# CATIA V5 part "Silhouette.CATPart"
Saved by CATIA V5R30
Part number: Part1
Bounding box of the stored display mesh (mm): x -117 to 50, y -75 to 75, z 0 to 147
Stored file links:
  D:\PROJECTS\CATIA V56R 2020\Resources\Parts File\c17_catia_v6_6r2020_prt\Silhouette.CATPart
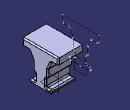
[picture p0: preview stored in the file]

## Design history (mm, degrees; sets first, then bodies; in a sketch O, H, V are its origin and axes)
Set1
  Sketch1 on yz-plane, origin (0, 0, 0), H (0, 1, 0), V (0, 0, 1)
    line L1 (0, 0) -> (45, 0)
    line L2 (45, 0) -> (45, 15)
    line L3 (45, 15) -> (22, 15)
    point P1 (45, 0)
    point P2 (45, 15)
    reference intersected line E1 through (0, 0) direction (0, 1) from zx-plane
    point P5 (0, 0)
    construction line L4 through (0, 0) direction (-1, 0)
    construction line L5 through (0, 0) direction (0, 1)
    point P6 (-45, 0)
    point P7 (-45, 15)
    line L6 (0, 0) -> (-45, 0)
    line L7 (-45, 0) -> (-45, 15)
    line L8 (-45, 15) -> (-22, 15)
    point P8 (-75, 147)
    line L9 (-75, 147) -> (75, 147)
    point P9 (75, 147)
    line L10 (75, 147) -> (75, 117)
    point P10 (75, 117)
    line L11 (75, 117) -> (45, 117)
    point P11 (45, 117)
    line L12 (45, 117) -> (30, 85)
    point P12 (30, 85)
    line L13 (30, 85) -> (30, 50)
    point P13 (30, 50)
    line L14 (30, 50) -> (22, 50)
    point P14 (22, 50)
    line L15 (22, 50) -> (22, 15)
    point P15 (22, 15)
    point P16 (-45, 15)
    point P17 (-75, 147)
    point P18 (-75, 117)
    point P19 (-45, 117)
    point P20 (-30, 85)
    point P21 (-30, 50)
    point P22 (-22, 50)
    point P23 (-22, 15)
    line L16 (-75, 147) -> (-75, 117)
    line L17 (-75, 117) -> (-45, 117)
    line L18 (-45, 117) -> (-30, 85)
    line L19 (-30, 85) -> (-30, 50)
    line L20 (-30, 50) -> (-22, 50)
    line L21 (-22, 50) -> (-22, 15)
    length L2 = 15
    length L10 = 30
    length L9 = 150
    length L11 = 30
    length L13 = 35
    length L15 = 35
    length L14 = 8
    distance P11 P12 V = 32
    distance P12 P11 H = 15
    horizontal: L1 H, L3 H, L9 H, L11 H, L14 H
    vertical: L2 V, L10 V, L13 V, L15 V
    symmetry: O P5 E1, H L4 E1, V L5 E1, P1 P6 E1, P2 P7 E1, L1 L6 E1, L2 L7 E1, L3 L8 E1, P2 P16 L5, P9 P17 L5, P10 P18 L5, P11 P19 L5, P12 P20 L5, P13 P21 L5, P14 P22 L5, P15 P23 L5, L10 L16 L5, L11 L17 L5, L12 L18 L5, L13 L19 L5, L14 L20 L5, L15 L21 L5, P9 P8 L5
    coincidence: P11 L2, O P5, P8 P17
Body1 (main body)
  Pad1: profile Sketch1, direction (1, 0, 0), length 50, mirrored extent
  Fillet1: radius 5, on edge [face of Pad1 from Sketch1.L10 | end face of Pad1]; edge [face of Pad1 from Sketch1.L16 | end face of Pad1]; edge [face of Pad1 from Sketch1.L17 | end face of Pad1]; edge [face of Pad1 from Sketch1.L18 | end face of Pad1]; edge [face of Pad1 from Sketch1.L19 | end face of Pad1]; edge [face of Pad1 from Sketch1.L20 | end face of Pad1]; edge [face of Pad1 from Sketch1.L21 | end face of Pad1]; edge [face of Pad1 from Sketch1.L8 | end face of Pad1]; edge [face of Pad1 from Sketch1.L3 | end face of Pad1]; edge [face of Pad1 from Sketch1.L15 | end face of Pad1]; edge [face of Pad1 from Sketch1.L14 | end face of Pad1]; end face of Pad1; edge [face of Pad1 from Sketch1.L10 | face of Pad1 from Sketch1.L11]; edge [face of Pad1 from Sketch1.L17 | face of Pad1 from Sketch1.L16]; edge [face of Pad1 from Sketch1.L11 | face of Pad1 from Sketch1.L12]; edge [face of Pad1 from Sketch1.L12 | face of Pad1 from Sketch1.L13]; edge [face of Pad1 from Sketch1.L13 | face of Pad1 from Sketch1.L14]; edge [face of Pad1 from Sketch1.L14 | face of Pad1 from Sketch1.L15]; edge [face of Pad1 from Sketch1.L15 | face of Pad1 from Sketch1.L3]; edge [face of Pad1 from Sketch1.L18 | face of Pad1 from Sketch1.L17]; edge [face of Pad1 from Sketch1.L19 | face of Pad1 from Sketch1.L18]; edge [face of Pad1 from Sketch1.L20 | face of Pad1 from Sketch1.L19]; edge [face of Pad1 from Sketch1.L21 | face of Pad1 from Sketch1.L20]; edge [face of Pad1 from Sketch1.L8 | face of Pad1 from Sketch1.L21]; face of Pad1 from Sketch1.L3; edge [face of Pad1 from Sketch1.L7 | face of Pad1 from Sketch1.L8]; edge [face of Pad1 from Sketch1.L2 | face of Pad1 from Sketch1.L1]; edge [face of Pad1 from Sketch1.L6 | face of Pad1 from Sketch1.L7]
  Plane1: type Offset, RefPlane start face of Pad1, Offset 67, reversed
  Silhouette1: Direction yz-plane, ShadowPlane Plane1, Support Fillet1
